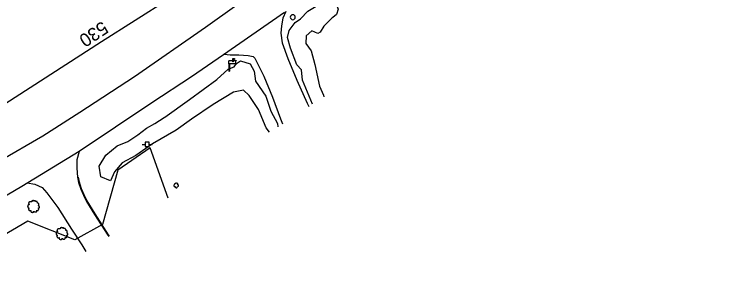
# Model space of a CAD drawing. Extents: x 1901471 to 1963503, y 756461 to 799997.
# Drawn here: x 1927611.3 to 1928043.7, y 771738.2 to 771903.5 of the extents above; entities that cross this region are included whole.
import ezdxf

# ---------------------------------------------------------------- set-up
doc = ezdxf.new("R2010")
doc.units = 0
for name, color, linetype in [('Default', 7, 'Continuous'), ('RD_EX_BldgApp', 7, 'Continuous'), ('RD_EX_Conc', 7, 'Continuous'), ('RD_EX_Fence_Other', 7, 'Continuous'), ('RD_EX_Misc', 7, 'Continuous'), ('RD_EX_Road', 7, 'Continuous'), ('RD_EX_UT', 7, 'Continuous'), ('RD_EX_VEG', 7, 'Continuous'), ('RD_HC_TX_Sta50', 7, 'Continuous')]:
    doc.layers.add(name, color=color, linetype=linetype)

# ---------------------------------------------------------------- blocks, each defined once
blk = doc.blocks.new('PP')
at = {"layer": 'RD_EX_UT'}
for p, q in [((2.49, 2.51), (-2.51, 2.51)), ((-2.51, 2.51), (-2.51, -2.49)), ((2.49, -2.49), (2.49, 2.51)), ((-5.94, -0.05), (-2.47, -0.05)), ((-2.51, -2.49), (2.49, -2.49)), ((2.42, -0.05), (6.06, -0.05))]:
    blk.add_line(p, q, dxfattribs=at)
blk = doc.blocks.new('POST')
at = {"layer": 'Default'}
for start, end in [(90, 270), (270, 90)]:
    blk.add_arc((0, 0), 0.127, start, end, dxfattribs=at)
blk = doc.blocks.new('MAIL')
at = {"layer": 'RD_EX_BldgApp'}
for p, q in [((-4.97, 0), (-4.97, 3.5)), ((-4.97, 0), (-4.97, -8.82)), ((2.59, 0), (-4.97, 0)), ((-4.47, 4), (2.59, 4)), ((-4.14, 0), (-4.14, -8.82)), ((-0.33, 6.48), (1.72, 6.48)), ((-0.33, 2.29), (-0.33, 6.48)), ((0.05, 2.29), (-0.33, 2.29)), ((1.72, 5.13), (0.05, 5.13)), ((0.05, 5.13), (0.05, 2.29)), ((1.72, 6.48), (1.72, 5.13)), ((3.09, 3.5), (3.09, 4)), ((3.09, 4), (3.59, 4)), ((3.09, 3.5), (3.09, 0.5)), ((3.59, 4), (3.59, 3.75)), ((-4.97, -8.82), (-4.14, -8.82))]:
    blk.add_line(p, q, dxfattribs=at)
for centre, start, end in [((-4.47, 3.5), 90, 180), ((2.59, 3.5), 0, 90), ((2.59, 0.5), 270, 0)]:
    blk.add_arc(centre, 0.5, start, end, dxfattribs=at)
blk = doc.blocks.new('T2')
at = {"layer": 'RD_EX_VEG'}
for points in [[(0.05, 7.21), (-0.25, 7.24), (-0.57, 7.14), (-0.82, 7.04), (-1.05, 6.96), (-1.27, 6.86), (-1.57, 6.69), (-1.8, 6.49), (-1.92, 6.24), (-1.97, 6.01), (-2.02, 5.74), (-2.02, 5.56), (-2.15, 5.54), (-2.3, 5.56), (-2.55, 5.64), (-2.8, 5.64), (-3.05, 5.64), (-3.4, 5.61), (-3.75, 5.61), (-4.02, 5.56), (-4.35, 5.51), (-4.72, 5.39), (-5.07, 5.26), (-5.37, 5.01), (-5.62, 4.54), (-5.75, 4.19), (-5.9, 3.94), (-5.75, 3.49), (-5.57, 3.14), (-5.55, 2.94), (-5.47, 2.52), (-5.37, 2.29), (-5.25, 2.09), (-5.32, 2.07), (-5.7, 2.02), (-6, 1.92), (-6.42, 1.69), (-6.64, 1.47), (-6.74, 1.14), (-6.77, 0.79), (-6.87, 0.59), (-6.94, 0.32), (-6.97, 0.24), (-7.02, -0.08), (-6.92, -0.53), (-6.89, -0.88), (-6.77, -1.11), (-6.62, -1.28), (-6.44, -1.53), (-6.05, -1.76), (-5.72, -1.86), (-5.52, -1.88), (-5.7, -2.38), (-5.75, -2.73), (-5.87, -3.13), (-5.87, -3.21), (-5.92, -3.68), (-5.77, -4.01), (-5.7, -4.38), (-5.52, -4.61), (-5.25, -4.91), (-4.92, -5.13), (-4.42, -5.26), (-4.02, -5.23), (-3.45, -5.06), (-3.2, -4.98), (-3.22, -5.16), (-3.2, -5.53), (-3.2, -5.96), (-3.05, -6.28), (-2.95, -6.56), (-2.8, -6.81), (-2.47, -7.03), (-2.07, -7.11), (-1.65, -7.26), (-1.2, -7.33), (-0.7, -7.36), (-0.1, -7.21), (0.18, -7.08), (0.28, -6.91), (0.48, -6.53), (0.43, -6.31), (0.45, -5.71), (0.55, -5.88), (0.73, -6.23), (1.23, -6.53), (1.63, -6.71), (2.1, -6.86), (2.4, -6.93), (2.88, -6.86), (3.25, -6.78), (3.63, -6.66), (3.93, -6.38), (4.1, -6.11), (4.15, -5.83), (4.23, -5.46), (4.28, -5.28)], [(4.28, -5.28), (4.2, -5.11), (4.15, -4.86), (4.23, -4.88), (4.4, -4.93), (4.68, -5.06), (4.9, -5.13), (5.23, -5.11), (5.5, -5.01), (5.95, -4.73), (6.22, -4.26), (6.5, -3.86), (6.57, -3.53), (6.52, -3.31), (6.5, -2.81), (6.3, -2.56), (6.25, -2.43), (6.15, -2.03), (6.22, -1.98), (6.5, -1.93), (6.87, -1.81), (7.15, -1.68), (7.37, -1.51), (7.45, -1.28), (7.42, -0.88), (7.47, -0.48), (7.4, -0.33), (7.3, -0.18), (7.22, 0.02), (7.07, 0.17), (6.97, 0.32), (6.87, 0.42), (6.75, 0.57), (6.57, 0.69), (6.42, 0.74), (6.37, 0.89), (6.52, 1.09), (6.57, 1.19), (6.6, 1.42), (6.82, 1.77), (6.87, 2.17), (6.82, 2.59), (6.77, 2.87), (6.62, 3.14), (6.42, 3.39), (6.3, 3.56), (6.12, 3.69), (5.8, 3.81), (5.55, 3.86), (5.2, 3.86), (5, 3.91), (5.03, 3.96), (5.03, 4.11), (5.03, 4.39), (4.95, 4.84), (4.8, 5.34), (4.8, 5.36), (4.7, 5.61), (4.48, 5.81), (4.3, 5.91), (4.1, 6.04), (3.85, 6.06), (3.55, 6.06), (3.28, 6.01), (3.08, 5.91), (2.9, 5.79), (2.83, 5.94), (2.73, 6.24), (2.68, 6.39), (2.53, 6.56), (2.3, 6.76), (1.85, 6.89), (1.23, 6.81), (0.93, 6.61), (0.78, 6.44), (0.73, 6.56), (0.53, 6.76), (0.43, 6.94), (0.25, 7.06), (0.1, 7.16), (0, 7.21)]]:
    blk.add_spline(points, degree=3, dxfattribs=at)
blk = doc.blocks.new('SB2')
at = {"layer": 'RD_EX_VEG'}
for centre, radius, start, end in [((-1.56, -0.16), 1.26, 96.45179, 294.73401), ((-0.72, 1.55), 1.08, 34.97629, 204.75602), ((1.05, 1.7), 0.995, 308.76261, 152.04674), ((1.84, -0.28), 1.22, 256.56668, 98.10463), ((0.25, -1.6), 1.32, 166.88266, 5.75893)]:
    blk.add_arc(centre, radius, start, end, dxfattribs=at)

msp = doc.modelspace()

# ---------------------------------------------------------------- linework, layer by layer
at = {"layer": 'RD_EX_Conc'}
msp.add_lwpolyline([(1927668.8, 771769.37), (1927668.22, 771770.27), (1927660.24, 771782.78), (1927655.37, 771790.66), (1927653.59, 771794.34), (1927651.95, 771797.99), (1927650.61, 771801.96), (1927650.07, 771805.07)], dxfattribs=at)
at = {"layer": 'RD_EX_Fence_Other'}
for points in [[(1928053.03, 772134.41), (1927953.68, 772074.71), (1927867.7, 772019.86), (1927787.61, 771967.65), (1927724.95, 771925.8), (1927664.08, 771886.9), (1927577.54, 771831.2), (1927486.71, 771772.85), (1927424.32, 771732.49), (1927359.11, 771690.15), (1927293.82, 771647.85), (1927228.56, 771605.61), (1927250.43, 771560.14), (1927272.23, 771514.18), (1927274.49, 771509.33)], [(1927704.3, 771792.44), (1927693.34, 771822.82), (1927673.82, 771809.23), (1927664.57, 771776.42), (1927647.95, 771767.24), (1927619.56, 771778.5), (1927570.46, 771749.92), (1927518.43, 771719.56), (1927525.28, 771699.72), (1927532.54, 771701.67), (1927538.31, 771684.61), (1927531.06, 771682.24), (1927531.88, 771679.87)]]:
    msp.add_lwpolyline(points, dxfattribs=at)
at = {"layer": 'RD_EX_Road'}
for points in [[(1927763.39, 771921.76), (1927726.89, 771895.55), (1927683.85, 771865.61), (1927650.88, 771844.05), (1927628.48, 771829.91), (1927601.91, 771814.41)], [(1927596.86, 771788.62), (1927615.88, 771799.6), (1927650.58, 771820.67), (1927694.49, 771850.2), (1927718.3, 771865.95), (1927737.82, 771879.12), (1927774.59, 771904.67)], [(1927775.4, 771905.23), (1927773.69, 771901.17), (1927772.76, 771896.58), (1927772.44, 771892.02), (1927773.17, 771886.24), (1927776.58, 771876.8), (1927782.12, 771863.66), (1927788.3, 771849.74), (1927789.34, 771847.7)], [(1927738.05, 771879.28), (1927741.69, 771879.06), (1927746.93, 771878.91), (1927752.71, 771878.64), (1927755.58, 771877.99), (1927756.58, 771876.97), (1927762.01, 771866.1), (1927767.31, 771853.4), (1927772.27, 771840.32), (1927773.41, 771837.34)], [(1927650.43, 771820.58), (1927649.04, 771815.61), (1927649.04, 771810.45), (1927649.58, 771804.98), (1927650.12, 771801.84), (1927651.48, 771797.8), (1927653.13, 771794.13), (1927654.94, 771790.42), (1927659.81, 771782.51), (1927667.8, 771770), (1927668.38, 771769.1)], [(1927619.04, 771801.52), (1927623.76, 771800.84), (1927628.08, 771798.7), (1927631.03, 771795.51), (1927637.53, 771786.77), (1927645.94, 771773.52), (1927652.04, 771764.18), (1927654.56, 771760.12)]]:
    msp.add_lwpolyline(points, dxfattribs=at)
at = {"layer": 'RD_EX_VEG'}
for points in [[(1927791.44, 771849.06), (1927785.45, 771863.66), (1927784.89, 771869.92), (1927782.07, 771872.99), (1927778.32, 771883.1), (1927776.36, 771889.45), (1927777.39, 771893.73), (1927781, 771898.6), (1927784.17, 771900.77), (1927788.63, 771905.33), (1927795.83, 771909.66), (1927800.49, 771911.87), (1927802.98, 771911.82), (1927806.27, 771908.67), (1927807.13, 771906.48), (1927806.04, 771903.29), (1927803.71, 771901.52), (1927803.12, 771901.19)], [(1927803.12, 771901.19), (1927798.36, 771896.37), (1927796.18, 771892.59), (1927794.67, 771891.78), (1927791.17, 771893.51), (1927787.67, 771890.38), (1927787.44, 771885.81), (1927790.65, 771881.3), (1927792.86, 771873.13), (1927795.83, 771860.07), (1927798.09, 771854.52), (1927798.34, 771853.54)], [(1927702.25, 771841.36), (1927717.14, 771851.99), (1927733.76, 771864.16), (1927740.64, 771870.29), (1927744.09, 771871.67), (1927745.52, 771873.69), (1927748.04, 771875.37), (1927753.79, 771873.57), (1927756.34, 771869.12), (1927757.15, 771863.14), (1927763.41, 771854.04), (1927766.4, 771845.01), (1927770.39, 771837.4), (1927770.49, 771835.45)], [(1927765.47, 771832.18), (1927763.42, 771834.8), (1927758.85, 771845.91), (1927753.34, 771854.42), (1927749.88, 771857.64), (1927743.82, 771856.36), (1927731.5, 771848.87), (1927718.33, 771840.05), (1927709.16, 771833.38), (1927694.73, 771825.12), (1927684.66, 771818.06), (1927676.41, 771813.67), (1927671.94, 771808.18), (1927669.47, 771802.84), (1927663.66, 771805.19), (1927662.62, 771811.62), (1927666.63, 771818.33), (1927673.47, 771823.98), (1927679.95, 771826.61), (1927686, 771830.64), (1927691.25, 771834.73), (1927696.13, 771837.45), (1927701.9, 771841.06), (1927702.25, 771841.36)]]:
    msp.add_lwpolyline(points, dxfattribs=at)

# ---------------------------------------------------------------- block references
at = {"layer": 'Default'}
for name, p, xscale, yscale in [('MAIL', (1927743.53, 771873.51), 0.5019685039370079, 0.5019685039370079), ('PP', (1927691.62, 771824.86), 0.5039370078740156, 0.5039370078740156)]:
    msp.add_blockref(name, p, dxfattribs=dict(at, xscale=xscale, yscale=yscale))
at = {"layer": 'RD_EX_Misc', "xscale": 11.811023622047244, "yscale": 11.811023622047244}
msp.add_blockref('POST', (1927779.62, 771901.71), dxfattribs=at)
at = {"layer": 'RD_EX_VEG'}
for name, p, xscale, yscale in [('SB2', (1927709.06, 771800.04), 0.5019685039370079, 0.5019685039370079), ('T2', (1927622.81, 771787.39), 0.4921259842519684, 0.4921259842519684), ('T2', (1927639.95, 771771), 0.4921259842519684, 0.4921259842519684)]:
    msp.add_blockref(name, p, dxfattribs=dict(at, xscale=xscale, yscale=yscale))

# ---------------------------------------------------------------- texts
at = {"layer": 'RD_HC_TX_Sta50'}
msp.add_text('530', height=8, rotation=213.5419, dxfattribs=at).set_placement((1927664.56, 771899.67))

doc.saveas('drawing.dxf')
